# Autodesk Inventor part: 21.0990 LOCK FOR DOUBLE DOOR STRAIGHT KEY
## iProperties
Created: 2007-03
Part Number: 21.0990 LOCK FOR DOUBLE DOOR STRAIGHT KEY
Material: Steel
Document SubType Name: Modeling
Designer: Andy Moles
Density: 7.85 g/cm^3
Author: Andy Moles
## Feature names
1. Base1
